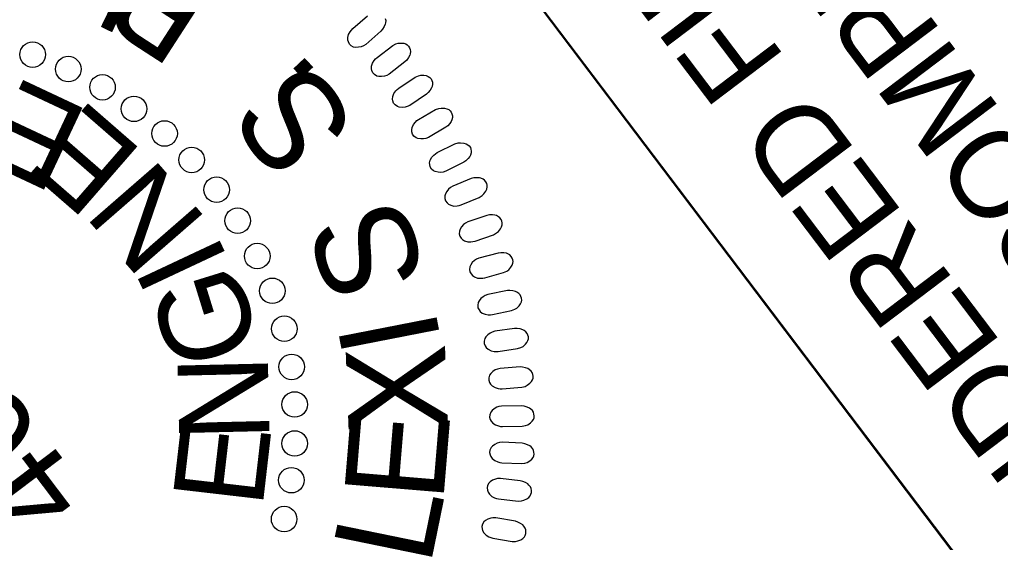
# Model space of a CAD drawing. Extents: x 475599 to 477488, y 499839 to 501843.
# Drawn here: x 475746.4 to 475807.9, y 501195.7 to 501228.5 of the extents above; entities that cross this region are included whole.
import ezdxf

# ---------------------------------------------------------------- set-up
doc = ezdxf.new("R2010")
doc.units = 0
for name, color, linetype in [('Sheet PE Seal Cell', 7, 'Continuous'), ('Sheet Plan CELL', 7, 'Continuous'), ('Sheet Sticker Exception Certification CELL', 7, 'Continuous'), ('Sheet Sticker Incomplete CELL', 7, 'Continuous')]:
    doc.layers.add(name, color=color, linetype=linetype)

msp = doc.modelspace()

# ---------------------------------------------------------------- linework, layer by layer
at = {"layer": 'Sheet PE Seal Cell'}
msp.add_lwpolyline([(475769.352, 501228.546), (475769.375, 501228.428), (475769.368, 501228.283), (475769.347, 501228.186), (475769.277, 501228.038), (475769.18, 501227.875), (475769.073, 501227.754), (475768.126, 501226.929), (475767.983, 501226.835), (475767.847, 501226.779), (475767.668, 501226.743), (475767.489, 501226.736), (475767.365, 501226.758), (475767.217, 501226.838), (475767.105, 501226.939), (475767.038, 501227.078), (475767.007, 501227.189), (475766.999, 501227.351), (475767.051, 501227.552), (475767.143, 501227.721), (475767.221, 501227.827), (475767.31, 501227.923), (475768.241, 501228.723)], dxfattribs=at)
for points in [[(475768.836, 501226.11), (475769.815, 501226.85), (475770.012, 501226.952), (475770.155, 501226.995), (475770.358, 501227.008), (475770.505, 501226.996), (475770.636, 501226.955), (475770.73, 501226.896), (475770.814, 501226.818), (475770.865, 501226.717), (475770.914, 501226.603), (475770.93, 501226.484), (475770.913, 501226.34), (475770.885, 501226.244), (475770.807, 501226.1), (475770.7, 501225.944), (475770.586, 501225.83), (475769.588, 501225.066), (475769.44, 501224.982), (475769.301, 501224.934), (475769.12, 501224.908), (475768.941, 501224.914), (475768.818, 501224.943), (475768.676, 501225.032), (475768.57, 501225.14), (475768.512, 501225.283), (475768.488, 501225.397), (475768.49, 501225.558), (475768.554, 501225.755), (475768.657, 501225.918), (475768.742, 501226.019)], [(475770.199, 501224.19), (475771.223, 501224.867), (475771.426, 501224.957), (475771.571, 501224.991), (475771.775, 501224.991), (475771.92, 501224.971), (475772.048, 501224.921), (475772.139, 501224.856), (475772.218, 501224.772), (475772.262, 501224.668), (475772.304, 501224.552), (475772.312, 501224.432), (475772.286, 501224.29), (475772.253, 501224.195), (475772.165, 501224.057), (475772.049, 501223.908), (475771.928, 501223.801), (475770.884, 501223.101), (475770.731, 501223.027), (475770.589, 501222.987), (475770.407, 501222.974), (475770.228, 501222.989), (475770.108, 501223.027), (475769.972, 501223.125), (475769.873, 501223.239), (475769.823, 501223.386), (475769.808, 501223.5), (475769.82, 501223.661), (475769.896, 501223.854), (475770.008, 501224.01), (475770.1, 501224.106)], [(475771.44, 501222.223), (475772.504, 501222.834), (475772.713, 501222.911), (475772.86, 501222.936), (475773.063, 501222.924), (475773.206, 501222.894), (475773.332, 501222.836), (475773.418, 501222.766), (475773.491, 501222.678), (475773.53, 501222.571), (475773.564, 501222.452), (475773.564, 501222.332), (475773.529, 501222.192), (475773.49, 501222.1), (475773.394, 501221.967), (475773.268, 501221.826), (475773.141, 501221.727), (475772.056, 501221.094), (475771.898, 501221.029), (475771.754, 501220.998), (475771.571, 501220.996), (475771.394, 501221.023), (475771.277, 501221.068), (475771.146, 501221.174), (475771.055, 501221.294), (475771.015, 501221.444), (475771.006, 501221.559), (475771.028, 501221.719), (475771.116, 501221.906), (475771.238, 501222.055), (475771.336, 501222.146)], [(475772.608, 501220.14), (475773.709, 501220.683), (475773.921, 501220.747), (475774.07, 501220.762), (475774.272, 501220.737), (475774.413, 501220.698), (475774.534, 501220.633), (475774.616, 501220.557), (475774.684, 501220.465), (475774.715, 501220.356), (475774.742, 501220.235), (475774.735, 501220.115), (475774.691, 501219.977), (475774.647, 501219.888), (475774.542, 501219.761), (475774.408, 501219.628), (475774.275, 501219.537), (475773.152, 501218.974), (475772.989, 501218.919), (475772.844, 501218.898), (475772.662, 501218.907), (475772.487, 501218.946), (475772.372, 501218.997), (475772.249, 501219.111), (475772.165, 501219.237), (475772.135, 501219.389), (475772.133, 501219.505), (475772.165, 501219.662), (475772.265, 501219.844), (475772.396, 501219.985), (475772.499, 501220.068)], [(475774.106, 501216.856), (475775.238, 501217.33), (475775.425, 501217.448), (475775.535, 501217.55), (475775.648, 501217.72), (475775.712, 501217.852), (475775.741, 501217.986), (475775.738, 501218.098), (475775.713, 501218.209), (475775.651, 501218.304), (475775.577, 501218.403), (475775.482, 501218.477), (475775.35, 501218.535), (475775.253, 501218.56), (475775.089, 501218.563), (475774.9, 501218.549), (475774.744, 501218.508), (475773.582, 501218.031), (475773.435, 501217.944), (475773.323, 501217.849), (475773.211, 501217.704), (475773.125, 501217.547), (475773.089, 501217.427), (475773.094, 501217.259), (475773.134, 501217.114), (475773.229, 501216.99), (475773.315, 501216.914), (475773.456, 501216.834), (475773.658, 501216.79), (475773.85, 501216.797), (475773.981, 501216.82)], [(475774.977, 501214.59), (475776.137, 501214.991), (475776.332, 501215.099), (475776.447, 501215.193), (475776.571, 501215.355), (475776.642, 501215.483), (475776.681, 501215.615), (475776.684, 501215.726), (475776.666, 501215.839), (475776.611, 501215.938), (475776.543, 501216.042), (475776.453, 501216.122), (475776.324, 501216.187), (475776.229, 501216.218), (475776.065, 501216.232), (475775.877, 501216.23), (475775.718, 501216.199), (475774.528, 501215.795), (475774.375, 501215.718), (475774.259, 501215.63), (475774.137, 501215.493), (475774.042, 501215.342), (475773.998, 501215.223), (475773.993, 501215.056), (475774.023, 501214.908), (475774.11, 501214.779), (475774.192, 501214.697), (475774.327, 501214.609), (475774.526, 501214.552), (475774.718, 501214.548), (475774.85, 501214.562)], [(475775.591, 501212.284), (475776.773, 501212.612), (475776.975, 501212.707), (475777.096, 501212.794), (475777.229, 501212.948), (475777.309, 501213.071), (475777.355, 501213.2), (475777.366, 501213.312), (475777.355, 501213.426), (475777.306, 501213.527), (475777.245, 501213.635), (475777.16, 501213.72), (475777.035, 501213.794), (475776.943, 501213.831), (475776.781, 501213.855), (475776.592, 501213.865), (475776.432, 501213.844), (475775.219, 501213.515), (475775.062, 501213.449), (475774.94, 501213.367), (475774.809, 501213.239), (475774.705, 501213.094), (475774.654, 501212.978), (475774.638, 501212.811), (475774.659, 501212.661), (475774.738, 501212.529), (475774.814, 501212.441), (475774.943, 501212.345), (475775.139, 501212.275), (475775.33, 501212.258), (475775.463, 501212.264)], [(475776.072, 501209.979), (475777.272, 501210.233), (475777.478, 501210.314), (475777.604, 501210.394), (475777.748, 501210.539), (475777.835, 501210.657), (475777.889, 501210.783), (475777.907, 501210.893), (475777.903, 501211.008), (475777.86, 501211.113), (475777.807, 501211.224), (475777.727, 501211.314), (475777.607, 501211.396), (475777.517, 501211.438), (475777.357, 501211.473), (475777.169, 501211.495), (475777.008, 501211.484), (475775.777, 501211.232), (475775.615, 501211.174), (475775.489, 501211.101), (475775.35, 501210.981), (475775.237, 501210.843), (475775.179, 501210.731), (475775.153, 501210.565), (475775.164, 501210.414), (475775.234, 501210.277), (475775.305, 501210.184), (475775.428, 501210.08), (475775.618, 501209.999), (475775.809, 501209.97), (475775.941, 501209.968)], [(475776.432, 501207.67), (475777.646, 501207.847), (475777.858, 501207.916), (475777.988, 501207.987), (475778.14, 501208.123), (475778.235, 501208.235), (475778.297, 501208.357), (475778.322, 501208.466), (475778.325, 501208.581), (475778.289, 501208.688), (475778.242, 501208.802), (475778.168, 501208.898), (475778.054, 501208.986), (475777.967, 501209.034), (475777.809, 501209.079), (475777.622, 501209.112), (475777.461, 501209.112), (475776.217, 501208.937), (475776.053, 501208.89), (475775.921, 501208.826), (475775.776, 501208.714), (475775.654, 501208.584), (475775.589, 501208.476), (475775.552, 501208.311), (475775.554, 501208.161), (475775.615, 501208.019), (475775.68, 501207.922), (475775.797, 501207.811), (475775.982, 501207.717), (475776.169, 501207.676), (475776.301, 501207.665)], [(475776.681, 501205.327), (475777.904, 501205.428), (475778.119, 501205.483), (475778.254, 501205.546), (475778.414, 501205.672), (475778.515, 501205.778), (475778.585, 501205.896), (475778.617, 501206.004), (475778.627, 501206.117), (475778.598, 501206.227), (475778.559, 501206.344), (475778.49, 501206.443), (475778.383, 501206.539), (475778.298, 501206.593), (475778.144, 501206.648), (475777.96, 501206.692), (475777.799, 501206.702), (475776.546, 501206.606), (475776.379, 501206.569), (475776.243, 501206.513), (475776.092, 501206.411), (475775.962, 501206.288), (475775.89, 501206.184), (475775.843, 501206.023), (475775.836, 501205.872), (475775.888, 501205.727), (475775.946, 501205.626), (475776.055, 501205.508), (475776.234, 501205.403), (475776.419, 501205.35), (475776.551, 501205.331)], [(475776.702, 501202.958), (475777.929, 501202.982), (475778.147, 501203.023), (475778.286, 501203.078), (475778.453, 501203.193), (475778.561, 501203.293), (475778.639, 501203.407), (475778.677, 501203.512), (475778.694, 501203.625), (475778.672, 501203.736), (475778.639, 501203.855), (475778.578, 501203.959), (475778.476, 501204.061), (475778.396, 501204.12), (475778.244, 501204.184), (475778.064, 501204.24), (475777.904, 501204.26), (475776.648, 501204.243), (475776.478, 501204.217), (475776.339, 501204.169), (475776.182, 501204.077), (475776.044, 501203.963), (475775.967, 501203.864), (475775.909, 501203.705), (475775.892, 501203.555), (475775.935, 501203.406), (475775.988, 501203.303), (475776.089, 501203.178), (475776.261, 501203.062), (475776.442, 501202.998), (475776.573, 501202.971)], [(475776.66, 501200.692), (475777.886, 501200.639), (475778.107, 501200.667), (475778.248, 501200.713), (475778.423, 501200.817), (475778.536, 501200.91), (475778.621, 501201.018), (475778.666, 501201.121), (475778.691, 501201.233), (475778.675, 501201.345), (475778.65, 501201.466), (475778.596, 501201.573), (475778.5, 501201.682), (475778.423, 501201.746), (475778.277, 501201.819), (475778.1, 501201.887), (475777.941, 501201.916), (475776.686, 501201.978), (475776.516, 501201.963), (475776.374, 501201.924), (475776.211, 501201.842), (475776.067, 501201.736), (475775.982, 501201.642), (475775.916, 501201.488), (475775.89, 501201.339), (475775.923, 501201.189), (475775.969, 501201.081), (475776.063, 501200.95), (475776.227, 501200.824), (475776.404, 501200.748), (475776.531, 501200.713)], [(475776.46, 501198.422), (475777.68, 501198.291), (475777.902, 501198.305), (475778.046, 501198.342), (475778.227, 501198.436), (475778.347, 501198.521), (475778.438, 501198.624), (475778.488, 501198.723), (475778.52, 501198.833), (475778.512, 501198.946), (475778.495, 501199.069), (475778.447, 501199.179), (475778.358, 501199.293), (475778.286, 501199.361), (475778.144, 501199.445), (475777.972, 501199.523), (475777.816, 501199.563), (475776.567, 501199.703), (475776.396, 501199.699), (475776.252, 501199.669), (475776.084, 501199.597), (475775.934, 501199.5), (475775.844, 501199.412), (475775.767, 501199.262), (475775.732, 501199.115), (475775.756, 501198.963), (475775.794, 501198.853), (475775.879, 501198.716), (475776.036, 501198.58), (475776.207, 501198.493), (475776.333, 501198.45)], [(475776.089, 501195.965), (475777.299, 501195.758), (475777.521, 501195.758), (475777.667, 501195.786), (475777.854, 501195.868), (475777.978, 501195.945), (475778.076, 501196.042), (475778.133, 501196.139), (475778.171, 501196.246), (475778.17, 501196.36), (475778.161, 501196.483), (475778.12, 501196.596), (475778.039, 501196.716), (475777.971, 501196.788), (475777.834, 501196.88), (475777.667, 501196.969), (475777.514, 501197.018), (475776.277, 501197.237), (475776.105, 501197.243), (475775.96, 501197.222), (475775.788, 501197.161), (475775.631, 501197.074), (475775.537, 501196.992), (475775.451, 501196.847), (475775.406, 501196.703), (475775.42, 501196.549), (475775.452, 501196.437), (475775.529, 501196.295), (475775.676, 501196.149), (475775.842, 501196.052), (475775.964, 501196.001)]]:
    msp.add_lwpolyline(points, close=True, dxfattribs=at)
for centre in [(475747.235, 501226.284), (475749.469, 501225.377), (475751.616, 501224.235), (475753.589, 501222.882), (475755.507, 501221.337), (475757.21, 501219.68), (475758.77, 501217.815), (475760.092, 501215.87), (475761.319, 501213.653), (475762.267, 501211.475), (475763.017, 501209.097), (475763.481, 501206.702), (475763.665, 501204.345), (475763.666, 501201.9), (475763.46, 501199.597), (475763.007, 501197.158)]:
    msp.add_circle(centre, 0.801, dxfattribs=at)
at = {"layer": 'Sheet Plan CELL'}
for points in [[(477369.494, 500619.368), (476532.299, 499985.628), (475747.678, 501022.142), (475867.321, 501112.709), (475746.601, 501272.214), (476464.153, 501815.359)], [(475717.254, 501124.582), (475656.898, 501204.298), (475746.601, 501272.214), (475806.965, 501192.488)]]:
    msp.add_lwpolyline(points, close=True, dxfattribs=at)
at = {"layer": 'Sheet Sticker Exception Certification CELL'}
msp.add_line((475867.321, 501112.709), (475746.591, 501272.206), dxfattribs=at)
msp.add_line((475867.321, 501112.709), (475746.591, 501272.206), dxfattribs=at)

# ---------------------------------------------------------------- texts
at = {"layer": 'Sheet PE Seal Cell'}
for s, height, rotation, p in [('U', 6.236, 154.17136, (475755.509, 501233.021)), ('B', 6.236, 147.05452, (475759.317, 501230.611)), ('.', 6.236, 133.35191, (475765.356, 501224.946)), ('S', 6.236, 126.50625, (475767.755, 501221.696)), ('E', 5.669, 154.8474, (475750.918, 501222.686)), ('E', 5.669, 138.96781, (475754.27, 501220.118)), ('N', 5.669, 131.02801, (475758.283, 501215.822)), ('S', 6.236, 107.91105, (475772.011, 501212.224)), ('46155', 6.2363, 127.105, (475750.834, 501198.697)), ('I', 5.669, 115.14841, (475759.568, 501213.341)), ('G', 5.669, 107.20861, (475761.618, 501207.834)), ('I', 6.236, 101.0654, (475772.867, 501208.287)), ('X', 6.236, 92.11807, (475773.293, 501202.654)), ('N', 5.669, 91.32902, (475762.102, 501202.061)), ('E', 6.236, 85.27242, (475772.976, 501198.147)), ('E', 5.669, 83.38922, (475761.637, 501197.778)), ('L', 6.236, 78.42676, (475772.156, 501194.124))]:
    msp.add_text(s, height=height, rotation=rotation, dxfattribs=at).set_placement(p)
at = {"layer": 'Sheet Sticker Exception Certification CELL'}
for s, p in [('UNLESS ALL SIGNATURES COMPLETED', (475872.93, 501137.021)), ('UNLESS ALL SIGNATURES COMPLETED', (475872.93, 501137.021)), ('DOCUMENT NOT CONSIDERED FINAL', (475862.853, 501135.754)), ('DOCUMENT NOT CONSIDERED FINAL', (475862.853, 501135.754))]:
    msp.add_text(s, height=5.5, rotation=127.12364, dxfattribs=at).set_placement(p)
at = {"layer": 'Sheet Sticker Incomplete CELL'}
for s, height, p in [('INCOMPLETE PLANS', 11.52, (475791.734, 501100.002)), ('DO NOT USE FOR R/W ACQUISITION', 5.76, (475795.314, 501106.788))]:
    msp.add_text(s, height=height, rotation=127.12364, dxfattribs=at).set_placement(p)

doc.saveas('drawing.dxf')
